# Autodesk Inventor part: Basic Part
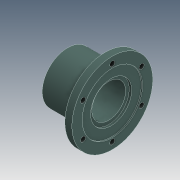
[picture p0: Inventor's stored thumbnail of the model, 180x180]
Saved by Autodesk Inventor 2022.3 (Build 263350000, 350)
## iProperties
Created: 2023-08
Part Number: Basic Part
Material: Generic
Document SubType Name: Modeling
Designer: irinventor.com
Density: 1 g/cm^3
Appearance: Default(1)
Author: irinventor.com
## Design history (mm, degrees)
sketch "Sketch1"
  geometry: L1 (10, 13.071)-(4, 13.071); L2 (4, 13.071)-(4, 8); L3 (4, 8)-(33.2, 8); L4 (35.2, 6)-(35.2, -4.429); L5 (35.2, -4.429)-(41, -4.429); L6 (10, 13.071)-(10, 15.071); L7 (10, 15.071)-(38, 15.071); L8 (38, 15.071)-(38, 12.071); L9 (38, 12.071)-(40, 12.071); L10 (40, 12.071)-(40, 4.071); L11 (40, 4.071)-(41, 4.071); L12 (41, 4.071)-(41, -4.429); L13 (46, 29.071)-(-12, 29.071); A1 r 2 centre (33.2, 6) between (35.2, 6) and (33.2, 8); 2 further points
  constraints: 26 end point, 7 horizontal, 5 vertical, 2 point on circle, 2 tangent, 1 centre point, 1 midpoint
  dimensions: "d0" = 28 distance of L6.end L7.end; "d1" = 6 distance of L1.start L1.end; "d2" = 28 diameter of L7 point (17, 29.071); "d3" = 2 radius of A1 (derived); "d4" = 1 distance between parallel lines of L12 L10; "d5" = 2 distance between parallel lines of L8 L10; "d6" = 34 diameter of L9 L13; "d7" = 67 diameter of L5 L13; "d9" = 32 diameter of L1 L13; "d18" = 31.2 distance between parallel lines of L2 L4; "d30" = 50 diameter of L11 L13
revolve "Revolution1" sketch "Sketch1" stored, may be unused: angle "d8" = 90 deg
workplane "Work Plane1"
sketch "Sketch2"
  geometry: L1 (14.6, -21.071)-(14.6, 21.071) reference; 2 further points
  constraints: 1 horizontal alignment
  dimensions: "d17" = 24 distance from line of L1 point (-9.4, 0)
hole "Hole1" sketch "Sketch2" at (-9.4, 0) diameter "d10" = 2.013; stored, may be unused: countersink angle "d14" = 90 deg, drill point angle "d16" = 118 deg; dims "d11" = 7, "d12" = 4, "d13" = 2, "d15" = 8
sketch "Sketch3"
  geometry: C1 r 23.071 at (0, 0) reference; 2 further points
  constraints: 1 vertical alignment
  dimensions: "d26" = 28 distance of point (0, 28) C1.centre
hole "Hole2" sketch "Sketch3" at (0, 28) diameter "d19" = 4.134; stored, may be unused: countersink angle "d23" = 90 deg, drill point angle "d25" = 118 deg; dims "d20" = 10, "d21" = 4, "d22" = 2, "d24" = 8
pattern_circular "Circular Pattern1" dims angle "d28" = 360 deg
body "Solid1"
